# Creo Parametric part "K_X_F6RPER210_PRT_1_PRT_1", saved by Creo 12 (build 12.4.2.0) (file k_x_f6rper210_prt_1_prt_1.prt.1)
Units: Custom; MM, KILOGRAM, SECS

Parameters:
  PTC_WM_ITERATION = "0"
  PTC_WM_VERSION = "-.0"
  PTC_WM_LIFECYCLE_STATE = "In Work"
  PTC_WM_LIFECYCLE = "MO_CADDocument"
  PTC_WM_CREATED_BY = "Maximilian Roepper (Z0017RMS: MO)"
  PTC_WM_CREATED_ON = "18-Sep-26 11:36:42 AM"
  PTC_WM_MODIFIED_BY = "Maximilian Roepper (Z0017RMS: MO)"
  PTC_WM_MODIFIED_ON = "18-Sep-26 11:36:46 AM"
  PDMLINKNUMBER = "PDM000071455179"
  PTC_WM_NAME = "k_x_f6rper210_prt_1_prt_1.prt"
  PTC_WM_NUMBER = "PDM000071455179"

Other parameters: WEIGHT, WEIGHT_FACTOR, WEIGHT_ADD, _MASS_TEMP, _DIFF_TEMP, MC_ERRORS, SUPPLIER

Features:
  1. coordinate system
  2. datum plane "PRT_YZ"
  3. datum plane "PRT_XY"
  4. datum plane "PRT_XZ"
  5. coordinate system
  6. datum axis
  7. datum axis
  8. datum axis
  9. coordinate system
  10. imported feature
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
Other named items: PRT, SIEMENS_MO, DRW_VIEW_ORG, PRT_X, PRT_Y, PRT_Z, CS0, ROUGH_GROB

Layers: 00_STD_CSYS-KSYS, 01_STD_PLANES-EBENEN, 02_STD_AXES-ACHSEN, 03_STD_CSYS-KSYS, 24_IMPORT_FEAT-IMPORT_KE

Surfaces: 14 plane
